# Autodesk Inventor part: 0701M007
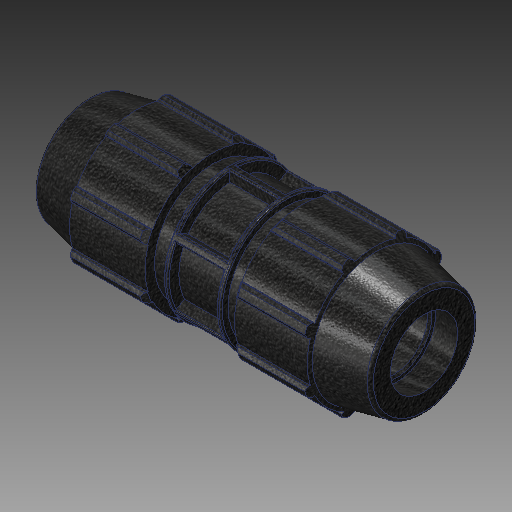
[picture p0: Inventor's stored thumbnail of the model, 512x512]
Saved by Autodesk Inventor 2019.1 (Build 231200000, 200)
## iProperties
Created: 2017-02
Part Number: 0701M007
Material: PVC-Piping
Description: PLASSON COUPLER 3/4'' - 25mm
Document SubType Name: Modeling
Designer: KIM
Mass: 92.6774 g
Surface Area: 199.44 cm^2
Volume: 66.1981 cm^3
Density: 1.4 g/cm^3
Appearance: PTFE
Author: KIM
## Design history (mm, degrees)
derived "0701M.ipt"
feature "Solid1::0701M.ipt"
tag "TaggingFeature1"
body "Solid1"
other parameters: "d2" = 25, "d4" = 10.414, "d5" = 17.85257, "d7" = 54.102, "d8" = 40.5765, "d9" = 17.85257, "d11" = 1.78526, "d12" = 43.2816, "d13" = 120 deg, "d14" = 39.9, "d15" = 12 deg, "d16" = 48.6918, "d18" = 1.33, "d19" = 35 deg, "d20" = 17.5 deg, "d21" = 50.31486, "d23" = 0, "d25" = 360 deg, "d27" = 1.08204, "d33" = 0.532, "d34" = 2.7051, "d36" = 0, "d37" = 0.532, "d38" = 0.532, "d40" = 360 deg, "d42" = 27.49296, "d43" = 1.62306, "d46" = 0.798, "d50" = 21.28, "d51" = 59.944, "d53" = 1.78526, "d54" = 27.49296, "d55" = 120 deg, "d56" = 12 deg, "d57" = 10.414, "d58" = 124.968, "d59" = 17.85257, "d63" = 17.85257, "d68" = 0, "d69" = 0.532, "d70" = 1.33, "d72" = 0, "d73" = 1.62306, "d77" = 59.944, "d78" = 26.6, "d_" = 26.6, "E_" = 54.102, "H_" = 124.968, "l_" = 59.944, "d_1" = 25
